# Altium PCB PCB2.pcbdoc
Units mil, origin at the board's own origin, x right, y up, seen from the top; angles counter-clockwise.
Board outline 3735.56 x 2015.12 mil, 2 copper layers (Top Layer, Bottom Layer); 65 components, 50 nets, 222 pads, 47 vias.
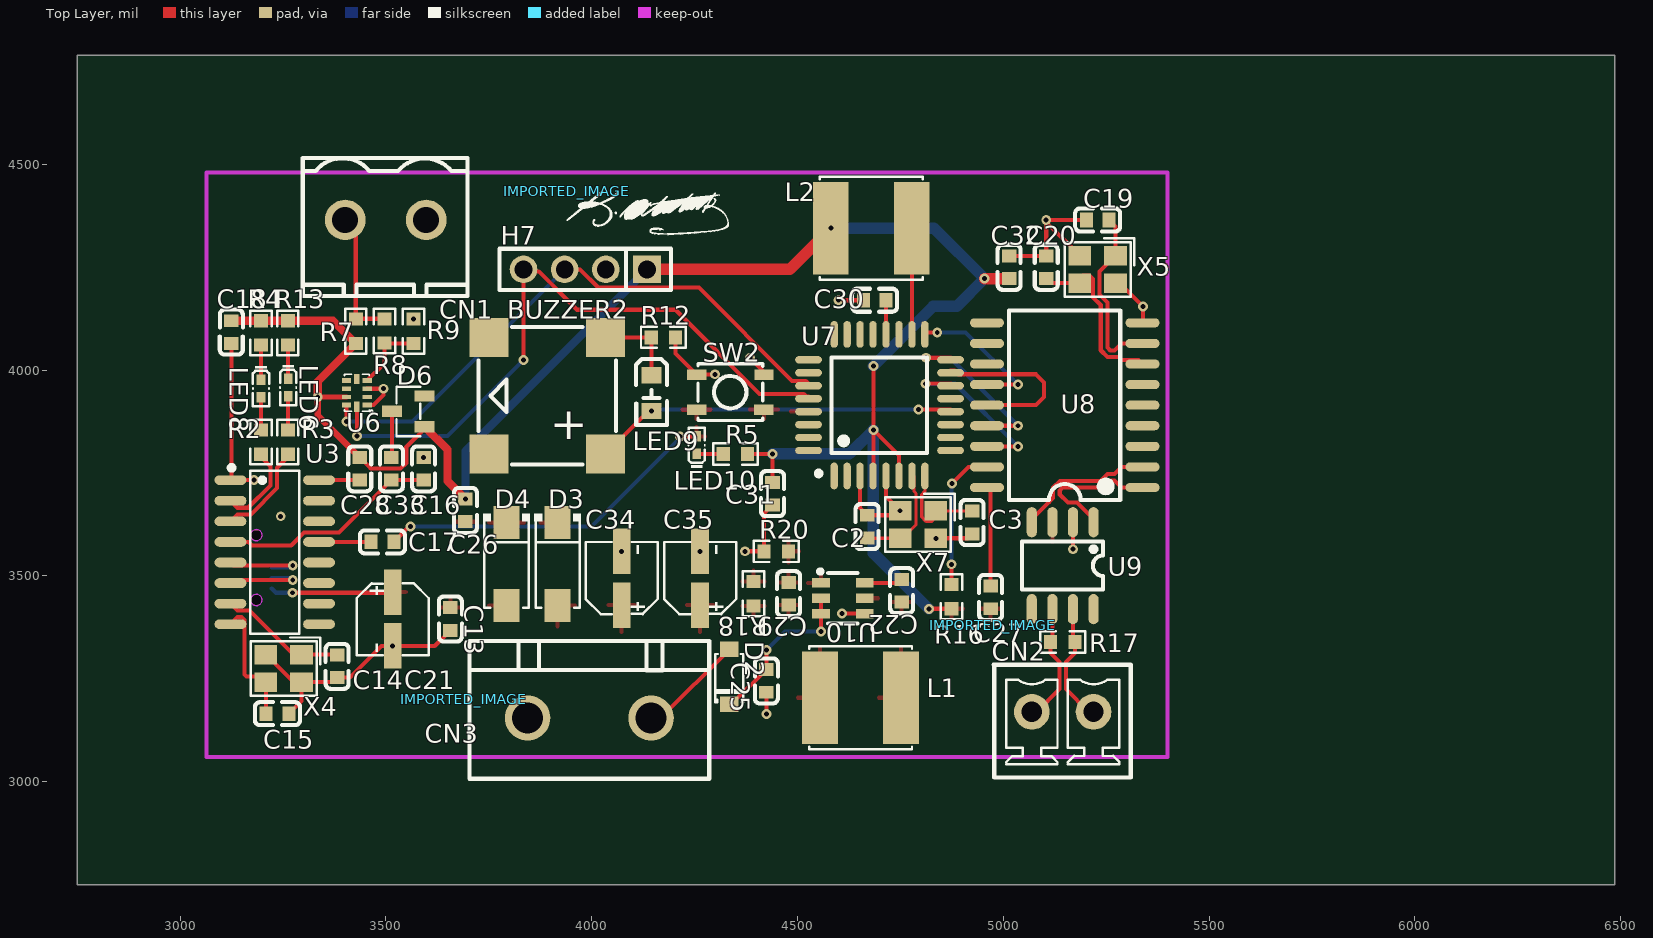
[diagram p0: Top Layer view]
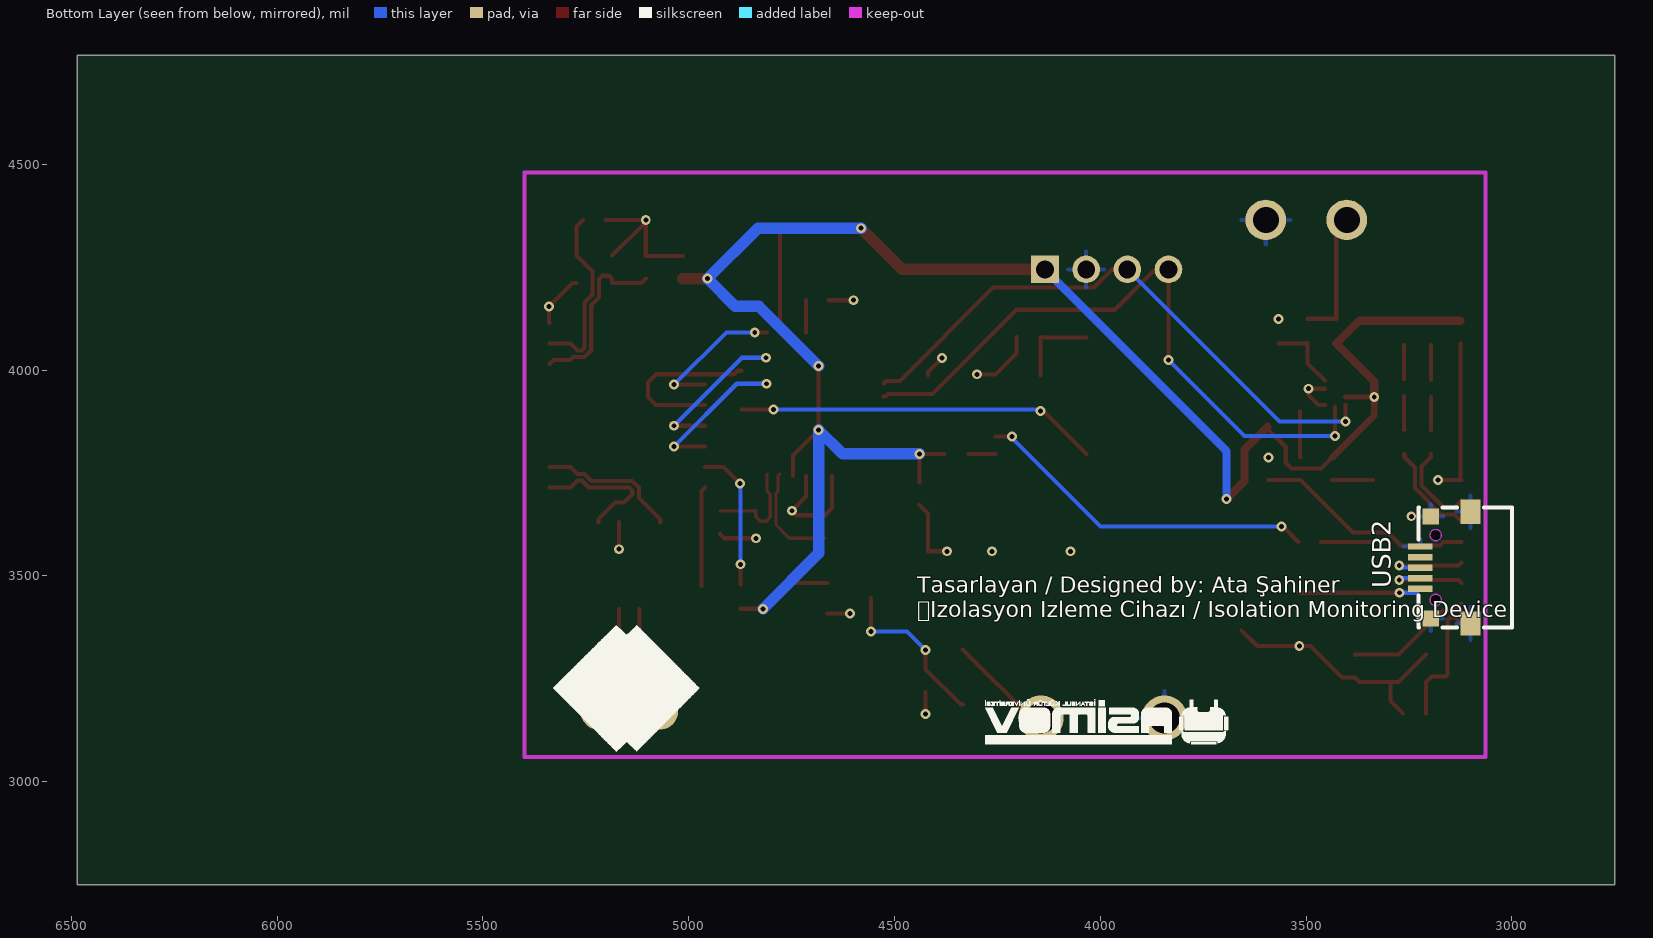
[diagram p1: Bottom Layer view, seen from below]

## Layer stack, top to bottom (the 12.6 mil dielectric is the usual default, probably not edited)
Top Layer: signal copper (thickness not stored)
Dielectric: dielectric 12.6, FR-4, Dk 4.8
Bottom Layer: signal copper (thickness not stored)

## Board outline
6485.56,2750 2750,2750 2750,4765.12 6485.56,4765.12

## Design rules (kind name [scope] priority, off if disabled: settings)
BoardOutlineClearance copperThickness1oz [All] p0: genericclearance=10 ignorepadtopadclearanceinfootprint=FALSE except(0: Arc-SplitContinuation Track-SplitContinuation SMDPad-SplitContinuation THPad-SplitContinuation Via-SplitContinuation Fill-SplitContinuation Poly-SplitContinuation Region-SplitContinuation Text-SplitContinuation; 6: Track-CutoutEdge SMDPad-CutoutEdge THPad-CutoutEdge Via-CutoutEdge Region-CutoutEdge; 11.8: Track-OutlineEdge SMDPad-OutlineEdge THPad-OutlineEdge Via-OutlineEdge Fill-OutlineEdge Region-OutlineEdge Poly-OutlineEdge Text-OutlineEdge Fill-CutoutEdge)
BoardOutlineClearance copperThickness2oz [All] p0: genericclearance=10 ignorepadtopadclearanceinfootprint=FALSE except(0: Arc-SplitContinuation Track-SplitContinuation SMDPad-SplitContinuation THPad-SplitContinuation Via-SplitContinuation Fill-SplitContinuation Poly-SplitContinuation Region-SplitContinuation Text-SplitContinuation; 6: Track-CutoutEdge SMDPad-CutoutEdge THPad-CutoutEdge Via-CutoutEdge Region-CutoutEdge; 11.8: Track-OutlineEdge SMDPad-OutlineEdge THPad-OutlineEdge Via-OutlineEdge Fill-OutlineEdge Region-OutlineEdge Poly-OutlineEdge Text-OutlineEdge Fill-CutoutEdge)
Clearance copperThickness1oz [(InNet('WARN') OR InNet('$1N38891') OR InNet('GND') OR InNet('XTAL1') OR InNet('XTAL2') OR InNet('$1N1971') OR InNet('$1N3263') OR InNet('$1N3302') OR InNet('RESET') OR InNet('+5V') OR InNet('$1N37233') OR InNet('$1N37305') OR InNet('$1N27741') OR InNet('$1N42220') OR InNet('$1N28334') OR InNet('$1N30372') OR InNet('$1N32358') OR InNet('$1N32397') OR InNet('$1N42230') OR InNet('$1N42278') OR InNet('$1N44015') OR InNet('$1N45861') OR InNet('$1N5233') OR InNet('$1N23722') OR InNet('$1N23715') OR InNet('$1N28331') OR InNet('SDA') OR InNet('SCL') OR InNet('$1N44013') OR InNet('$1N3088') OR InNet('TXD') OR InNet('$1N3089') OR InNet('RXD') OR InNet('$1N44197') OR InNet('AIN0') OR InNet('$1N13750') OR InNet('$1N2610') OR InNet('$1N2618') OR InNet('INT') OR InNet('AGND') OR InNet('SCK') OR InNet('SO') OR InNet('SI') OR InNet('CS') OR InNet('XI') OR InNet('XO') OR InNet('TXCAN') OR InNet('RXCAN') OR InNet('TXDC') OR InNet('RXDC'))] p1: gap=7 ignorepadtopadclearanceinfootprint=FALSE except(4: Track-Track; 6: Track-SMDPad SMDPad-SMDPad Track-THPad SMDPad-THPad THPad-THPad Track-Via SMDPad-Via THPad-Via Via-Via SMDPad-Fill THPad-Fill Via-Fill Fill-Fill Track-Region SMDPad-Region THPad-Region Via-Region Region-Region Track-Poly SMDPad-Poly THPad-Poly Via-Poly Fill-Poly Region-Poly Poly-Poly Track-Text SMDPad-Text THPad-Text Via-Text Fill-Text Region-Text Poly-Text Text-Text; 6.9: Track-Hole SMDPad-Hole THPad-Hole Via-Hole Fill-Hole Region-Hole Poly-Hole Text-Hole Sheet-Hole; 11.8: Track-Fill Fill-Region Track-Sheet SMDPad-Sheet THPad-Sheet Via-Sheet Fill-Sheet Region-Sheet Poly-Sheet Text-Sheet)
Clearance copperThickness2oz [All] p1: gap=7 ignorepadtopadclearanceinfootprint=FALSE except(6: Track-SMDPad SMDPad-SMDPad Track-THPad SMDPad-THPad THPad-THPad Track-Via SMDPad-Via THPad-Via Via-Via SMDPad-Fill THPad-Fill Via-Fill Fill-Fill Track-Region SMDPad-Region THPad-Region Via-Region Region-Region Track-Poly SMDPad-Poly THPad-Poly Via-Poly Fill-Poly Region-Poly Poly-Poly Track-Text SMDPad-Text THPad-Text Via-Text Fill-Text Region-Text Poly-Text Text-Text; 6.9: Track-Hole SMDPad-Hole THPad-Hole Via-Hole Fill-Hole Region-Hole Poly-Hole Text-Hole Sheet-Hole; 8: Track-Track; 11.8: Track-Fill Fill-Region Track-Sheet SMDPad-Sheet THPad-Sheet Via-Sheet Fill-Sheet Region-Sheet Poly-Sheet Text-Sheet)
DiffPairsRouting differentialPair [All] p1: maxuncoupledlength=10 minlimit=6 maxlimit=6 mostfreqgap=6 toplayer_minwidth=5 toplayer_prefwidth=10 toplayer_maxwidth=100 bottomlayer_minwidth=5 bottomlayer_prefwidth=10 bottomlayer_maxwidth=100
PasteMaskExpansion pasteMaskExpansion [All] p1: expansion=0
PlaneConnect innerPlane [All] p1: planeconnectstyle=Relief reliefexpansion=20 reliefentries=4 reliefconductorwidth=10 reliefairgap=10
PolygonConnect copperRegion [All] p1: connectstyle=Relief reliefentries=4 reliefconductorwidth=10 polygonreliefangle="90 Angle" airgapwidth=10
RoutingVias viaSize [All] p1: viastyle="Through Hole" holewidth=12.0078 minholewidth=11.811 maxholewidth=248.0314 width=24.0158 minwidth=19.685 maxwidth=393.7008
SolderMaskExpansion solderMaskExpansion [All] p1: useseparateexpansions=TRUE expansion=2 expansionbottom=2
Width copperThickness1oz [All] p1: maxlimit=100 minlimit=5 preferedwidth=10
Width copperThickness2oz [All] p1: maxlimit=100 minlimit=8 preferedwidth=10

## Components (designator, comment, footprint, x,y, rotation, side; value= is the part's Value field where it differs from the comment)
BUZZER2 "MLT-8530" BUZ-SMD_4P-L8.5-W8.5-P8.50-BR 3891.73,3937.78 r90 top
C2 "FCC1206N220J102DT" C0603 4669.23,3620 r90 top
C3 "FCC1206N220J102DT" C0603 4924.23,3630 r270 top
C13 "CC0603KRX7R9BB104" C0603 3656.42,3395.43 r90 top
C14 "FCC1206N220J102DT" C0603 3381.42,3280.43 r270 top
C15 "FCC1206N220J102DT" C0603 3236.42,3165.43 r0 top
C16 "CC0603KRX7R9BB104" C0603 3591.55,3760.31 r90 top
C17 "CC0603KRX7R9BB104" C0603 3491.42,3582.75 r180 top
C18 "CC0603KRX7R9BB104" C0603 3124.22,4092.52 r270 top
C19 "FCC1206N220J102DT" C0603 5229.23,4365 r180 top
C20 "FCC1206N220J102DT" C0603 5104.23,4250 r90 top
C21 "VT1H4R7M-CRC54" CAP-SMD_BD4.0-L4.3-W4.3-FD 3516.42,3395.43 r270 top
C22 "CC0603KRX7R9BB104" C0603 4753.06,3464.23 r90 top
C25 "CC0603KRX7R9BB104" C0603 4424.23,3245 r90 top
C26 "CC0603KRX7R9BB104" C0603 3693.06,3659.35 r90 top
C27 "CC0603KRX7R9BB104" C0603 4969.23,3447.92 r90 top
C28 "CC0603KRX7R9BB104" C0603 3436.42,3760.31 r90 top
C29 "CC0603KRX7R9BB104" C0603 4478.38,3456.97 r270 top
C30 "CC0603KRX7R9BB104" C0603 4687.41,4170 r0 top
C31 "CC0603KRX7R9BB104" C0603 4439.23,3700 r270 top
C32 "CC0603KRX7R9BB104" C0603 5014.23,4250 r270 top
C33 "CC0603KRX7R9BB104" C0603 3513.15,3760.31 r90 top
C34 "VT1H4R7M-CRC54" CAP-SMD_BD4.0-L4.3-W4.3-FD 4072.75,3494.54 r90 top
C35 "VT1H4R7M-CRC54" CAP-SMD_BD4.0-L4.3-W4.3-FD 4263.36,3494.54 r90 top
CN1 "WJ2EDGV-5.08-2P_C8461" CONN-TH_WJ2EDGV-5.08-2P 3499.35,4365.12 r180 top
CN2 "WJ15EDGVC-3.81-2P_C8396" CONN-TH_WJ15EDGVC-3.81-2P 5144.23,3170 r0 top
CN3 "DB2EVC-7.62-2P-GN" CONN-TH_2P-P7.62_DB2EVC-7.62-2P 3994.22,3155 r0 top
D2 "BZT52C5V6_C173406" SOD-123_L2.8-W1.8-LS3.7-RD 4334.23,3255 r90 top
D3 "SS14_R1_00001" SMA_L4.4-W2.8-LS5.4-RD 3917.07,3529.22 r270 top
D4 "SS14_R1_00001" SMA_L4.4-W2.8-LS5.4-RD 3793.06,3529.23 r270 top
D6 "BZX84C5V1_R1_00001" SOT-23-3_L2.9-W1.3-P1.90-LS2.4-BR 3554.22,3900 r0 top
H7 "HDR-F_2.54_1x4P" HDR-TH_4P-P2.54-V-F 3984.22,4245 r180 top
IMPORTED_IMAGE "IMPORTED_IMAGE" IMPORTED_IMAGE 4974.23,3380 r0 top
IMPORTED_IMAGE "IMPORTED_IMAGE" IMPORTED_IMAGE 3939.22,4435 r0 top
IMPORTED_IMAGE "IMPORTED_IMAGE" IMPORTED_IMAGE 3689.22,3200 r0 top
L1 "ASPI-0628-100M-T1" IND-SMD_L6.0-W6.0 4653.06,3204.23 r180 top
L2 "ASPI-0628-100M-T1" IND-SMD_L6.0-W6.0 4679.54,4345 r180 top
LED6 "LED_0402-R" LED0402-RD_YELLOW 3262.39,3957.81 r270 top
LED8 "LED_0402-R" LED0402-RD_YELLOW 3196.42,3955.43 r270 top
LED9 "YLED0805B" LED0805-RD 4145.17,3944.34 r270 top
LED10 "LED_0402-R" LED0402-RD_YELLOW 4254.89,3817.96 r90 top
R2 "1k" R0603 3196.42,3825.43 r270 top
R3 "1k" R0603 3261.42,3825.43 r270 top
R4 "1k" R0603 3196.42,4090.43 r90 top
R5 "10k" R0603 4349.23,3796.77 r0 top
R7 "1M" R0603 3426.62,4094.88 r90 top
R8 "1M" R0603 3496.28,4095.22 r270 top
R9 "82k" R0603 3566.62,4094.88 r90 top
R12 "220" R0603 4174.23,4080 r180 top
R13 "1k" R0603 3261.42,4090.43 r90 top
R16 "10k" R0603 4874.23,3450 r90 top
R17 "120" R0603 5144.23,3339.39 r0 top
R18 "576k" R0603 4393.07,3456.97 r270 top
R20 "113k" R0603 4448.06,3559.92 r180 top
SW2 "PTS810SJS250SMTRLFS" SW-SMD_4P_PTS810SJM250SMTRLFS 4336.67,3946.56 r0 top
U3 "CH340G" SOIC-16_L9.9-W3.9-P1.27-LS6.0-BL 3229.81,3557.76 r270 top
U6 "ADS1115IRUGR" X2QFN-10_L2.0-W1.5-P0.50-BL 3429.22,3945 r90 top
U7 "ATMEGA328P-AU_C14877" TQFP-32_L7.0-W7.0-P0.80-LS9.0-BL 4699.23,3915 r0 top
U8 "MCP2515T-I/SO" SOIC-18_L11.6-W7.5-P1.27-LS10.3-BL 5149.23,3915 r90 top
U9 "TJA1050DRG" SOP-8_L4.9-W3.9-P1.27-LS6.0-BL 5144.23,3525 r180 top
U10 "AP63200WU-7" SOT-23-6_L2.9-W1.6-P0.95-LS2.8-BR 4610.2,3445.84 r180 top
USB2 "MICRO QTZB5.5" MICRO-USB-SMD_MICRO-QTZB5.5 3161.42,3520.43 r90 bottom
X4 "TAXM8M4RDBCCT2T" CRYSTAL-SMD_4P-L3.2-W2.5-BL 3251.42,3275.43 r180 top
X5 "TAXM8M4RDBCCT2T" CRYSTAL-SMD_4P-L3.2-W2.5-BL 5229.23,4245 r180 top
X7 "TAXM8M4RDBCCT2T" CRYSTAL-SMD_4P-L3.2-W2.5-BL 4792.69,3625 r180 top

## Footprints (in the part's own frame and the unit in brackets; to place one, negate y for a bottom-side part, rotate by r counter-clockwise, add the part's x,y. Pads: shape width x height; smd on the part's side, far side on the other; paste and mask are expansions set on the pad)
BUZ-SMD_4P-L8.5-W8.5-P8.50-BR [mil]
  rect 94.49x94.49 smd: 1(-141.72,-141.73) 2(141.73,-141.73) 3(141.72,141.72) 4(-141.72,141.73)
  silkscreen extent -167,-167 167,167
C0603 [mm]
  rect 0.8x0.9 smd: 1(-0.7,0) 2(0.7,0)
  silkscreen extent -1.39,-0.71 1.39,0.71
CAP-SMD_BD4.0-L4.3-W4.3-FD [mm]
  rect 2.8x1.1 smd: 1(-1.661,0) 2(1.661,0)
  silkscreen extent -2.22,-2.23 2.24,2.23
CONN-TH_2P-P7.62_DB2EVC-7.62-2P [mm]
  round 2.8 hole 1.9: 1(-3.81,0) 2(3.81,0)
  silkscreen extent -7.4,-3.75 7.4,4.75
CONN-TH_WJ2EDGV-5.08-2P [mm]
  round 2.5 hole 1.6: 1(-2.499,0) 2(2.499,0)
  silkscreen extent -5.04,-3.81 5.12,4.7
CONN-TH_WJ15EDGVC-3.81-2P [mm]
  round 2.2 hole 1.25: 1(-1.905,0) 2(1.905,0)
  silkscreen extent -4.26,-4.06 4.2,2.9
CRYSTAL-SMD_4P-L3.2-W2.5-BL [mm]
  rect 1.4x1.2 smd: 1(-1.1,-0.85) 2(1.1,-0.85) 3(1.1,0.85) 4(-1.1,0.85)
  silkscreen extent -2.26,-1.91 2.03,1.68
HDR-TH_4P-P2.54-V-F [mm]
  rect 1.7x1.7 hole 1.1: 1(-3.81,0)
  round 1.7 hole 1.1: 2(-1.27,0) 3(1.27,0) 4(3.81,0)
  silkscreen extent -5.29,-1.27 5.29,1.27
IMPORTED_IMAGE [mil]
IND-SMD_L6.0-W6.0 [mm]
  rect 2.2x5.72 smd: 1(-2.5,0) 2(2.5,0)
  silkscreen extent -3.18,-3.18 3.18,3.18
LED0402-RD_YELLOW [mm]
  rect 0.636x0.54 smd: 1(-0.538,0) 2(0.538,0)
  silkscreen extent -1.39,-0.54 1.09,0.54
LED0805-RD [mm]
  rect 1x1.25 smd: 1(-1.1,0) 2(1.1,0)
  silkscreen extent -2.1,-0.95 1.98,0.96
MICRO-USB-SMD_MICRO-QTZB5.5 [mm]
  rect 0.4x1.524 smd: 1(-1.3,1.55) 2(-0.65,1.55) 3(0,1.55) 4(0.65,1.55) 5(1.3,1.55)
  rect 1.5x1.22 smd: 6(-3.45,-1.55) 7(3.45,-1.55)
  rect 1x1 smd: 6(-3.15,0.9) 7(3.15,0.9)
  Board Outline Layer circle w0.005: c-2,0.6 r0.35
  Board Outline Layer circle w0.005: c2,0.6 r0.35
  Board Outline Layer region: -2,0.95 -2.152,0.915 -2.274,0.818 -2.341,0.678 -2.341,0.522 -2.274,0.382 -2.152,0.285 -2,0.25 -2,0.25 -1.848,0.285 -1.726,0.382 -1.659,0.522 -1.659,0.678 -1.726,0.818 -1.848,0.915 -2,0.95
  Board Outline Layer region: 2,0.95 1.848,0.915 1.726,0.818 1.659,0.678 1.659,0.522 1.726,0.382 1.848,0.285 2,0.25 2,0.25 2.152,0.285 2.274,0.382 2.341,0.522 2.341,0.678 2.274,0.818 2.152,0.915 2,0.95
  Multi-Layer board cut-out: -2,0.95 -2.152,0.915 -2.274,0.818 -2.341,0.678 -2.341,0.522 -2.274,0.382 -2.152,0.285 -2,0.25 -2,0.25 -1.848,0.285 -1.726,0.382 -1.659,0.522 -1.659,0.678 -1.726,0.818 -1.848,0.915 -2,0.95
  Multi-Layer board cut-out: 2,0.95 1.848,0.915 1.726,0.818 1.659,0.678 1.659,0.522 1.726,0.382 1.848,0.285 2,0.25 2,0.25 2.152,0.285 2.274,0.382 2.341,0.522 2.341,0.678 2.274,0.818 2.152,0.915 2,0.95
  silkscreen extent -3.7,-4.1 3.7,1.65
R0603 [mil]
  rect 31.75x34.02 smd: 1(-29.66,0) 2(29.66,0)
  silkscreen extent -55,-26 55,26
SMA_L4.4-W2.8-LS5.4-RD [mil]
  rect 80.57x63.78 smd: 1(-101,0) 2(101,0)
  silkscreen extent -121,-57 106,57
SOD-123_L2.8-W1.8-LS3.7-RD [mm]
  rect 0.95x1.15 smd: 1(-1.692,0) 2(1.692,0)
  silkscreen extent -1.58,-0.87 1.41,0.87
SOIC-16_L9.9-W3.9-P1.27-LS6.0-BL [mil]
  oval 23.7x77.6 smd: 1(-175,-107.7) 2(-125,-107.7) 3(-75,-107.7) 4(-25,-107.7) 5(25,-107.7) 6(75,-107.7) 7(125,-107.7) 8(175,-107.7) 9(175,107.7) 10(125,107.7) 11(75,107.7) 12(25,107.7) 13(-25,107.7) 14(-75,107.7) 15(-125,107.7) 16(-175,107.7)
  silkscreen extent -211,-111 198,60
SOIC-18_L11.6-W7.5-P1.27-LS10.3-BL [mm]
  oval 0.56x2.1 smd: 1(-5.08,-4.8) 2(-3.81,-4.8) 3(-2.54,-4.8) 4(-1.27,-4.8) 5(0,-4.8) 6(1.27,-4.8) 7(2.54,-4.8) 8(3.81,-4.8) 9(5.08,-4.8) 10(5.08,4.8) 11(3.81,4.8) 12(2.54,4.8) 13(1.27,4.8) 14(0,4.8) 15(-1.27,4.8) 16(-2.54,4.8) 17(-3.81,4.8) 18(-5.08,4.8)
  silkscreen extent -5.84,-3.43 5.84,3.43
SOP-8_L4.9-W3.9-P1.27-LS6.0-BL [mm]
  oval 0.63x1.865 smd: 1(-1.905,-2.682) 2(-0.635,-2.682) 3(0.635,-2.682) 4(1.905,-2.682) 5(1.905,2.682) 6(0.635,2.682) 7(-0.635,2.682) 8(-1.905,2.682)
  silkscreen extent -2.5,-1.5 2.5,1.48
SOT-23-3_L2.9-W1.3-P1.90-LS2.4-BR [mm]
  rect 1.25x0.7 smd: 1(1,-0.95) 2(1,0.95) 3(-1,0)
  silkscreen extent -0.73,-1.53 0.73,1.53
SOT-23-6_L2.9-W1.6-P0.95-LS2.8-BR [mm]
  rect 1.1x0.6 smd: 1(1.35,-0.95) 2(1.35,0) 3(1.35,0.95) 4(-1.35,0.95) 5(-1.35,0) 6(-1.35,-0.95)
  silkscreen extent -0.9,-1.78 1.52,1.55
SW-SMD_4P_PTS810SJM250SMTRLFS [mm]
  rect 1.2x0.65 smd: 1(-2.078,1.083) 2(2.078,1.076) 3(-2.077,-1.083) 4(2.071,-1.075)
  silkscreen extent -2,-1.75 2,1.75
TQFP-32_L7.0-W7.0-P0.80-LS9.0-BL [mm]
  oval 0.45x1.65 smd: 1(-2.8,-4.369) 2(-2,-4.369) 3(-1.2,-4.369) 4(-0.4,-4.369) 5(0.4,-4.369) 6(1.2,-4.369) 7(2,-4.369) 8(2.8,-4.369) 17(2.8,4.369) 18(2,4.369) 19(1.2,4.369) 20(0.4,4.369) 21(-0.4,4.369) 22(-1.2,4.369) 23(-2,4.369) 24(-2.8,4.369)
  oval 1.65x0.45 smd: 9(4.381,-2.8) 10(4.381,-2) 11(4.381,-1.2) 12(4.381,-0.4) 13(4.381,0.4) 14(4.381,1.2) 15(4.381,2) 16(4.381,2.8) 25(-4.381,2.8) 26(-4.381,2) 27(-4.381,1.2) 28(-4.381,0.4) 29(-4.381,-0.4) 30(-4.381,-1.2) 31(-4.381,-2) 32(-4.381,-2.8)
  silkscreen extent -3.91,-4.36 2.94,2.95
X2QFN-10_L2.0-W1.5-P0.50-BL [mm]
  rect 0.3x0.58 smd: 1(-0.75,-0.635) 4(0.75,-0.635) 6(0.75,0.635) 9(-0.75,0.635)
  rect 0.25x0.58 smd: 2(-0.25,-0.635) 3(0.25,-0.635) 7(0.25,0.635) 8(-0.25,0.635)
  rect 0.63x0.35 smd: 5(0.86,0) 10(-0.86,0)
  silkscreen extent -1.22,-0.97 1.14,0.76

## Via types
v1: diameter 24.02, hole 12.01, Top Layer to Bottom Layer, 47 vias

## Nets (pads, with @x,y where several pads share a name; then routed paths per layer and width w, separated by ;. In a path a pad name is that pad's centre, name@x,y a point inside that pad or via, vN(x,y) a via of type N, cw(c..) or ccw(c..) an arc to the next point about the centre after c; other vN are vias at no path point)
$1N1971: C13.2 C21.1 D4.2 USB2.1 | length 298.8
  Top Layer w10: v1(3272.44,3459.25) 3514.86,3459.25 C21.1
  Bottom Layer w10: USB2.1 3232.44,3459.25 v1(3272.44,3459.25)
$1N2610: U3.5 USB2.3 | length 207.6
  Top Layer w10: U3.5 3129.45,3525.43 v1(3273.52,3525.43)
  Bottom Layer w10: USB2.3 3268.52,3520.43 v1(3273.52,3525.43)
$1N2618: U3.6 USB2.2 | length 207.5
  Top Layer w10: U3.6 3129.19,3489.84 v1(3273.52,3489.84)
  Bottom Layer w10: USB2.2 3268.52,3494.84 v1(3273.52,3489.84)
$1N3088: LED6.1 R13.1 | length 82.2
  Top Layer w10: R13.1 3262.39,4059.79 LED6.1
$1N3089: LED8.1 R4.1 | length 84.2
  Top Layer w10: LED8.1 R4.1
$1N3263: C16.1 C33.1 U3.4 | length 538.5
  Top Layer w10: U3.4 3166.42,3582.76 3174.78,3574.4 3269.91,3574.4 3301.1,3605.6 3386,3605.6 C33.1 C16.1
$1N3302: C17.2 U3.13 | length 126.3
  Top Layer w10: U3.13@3337.52,3582.75 C17.2
$1N5233: CN1.2 R7.2 R8.1 | length 321
  Top Layer w10: CN1.2 3426.62,4339.45 R7.2 3426.96,4124.88 R8.1
$1N13750: R16.2 U8.17 | length 347.3
  Top Layer w10: R16.2 v1(4874.23,3528.38) ; v1(4875.24,3725) 4915.24,3765 U8.17
  Bottom Layer w10: v1(4874.23,3528.38) 4874.23,3723.98 v1(4875.24,3725)
$1N23715: CN2.2 R17.2 U9.7 | length 295.1
  Top Layer w10: U9.7 5169.23,3350.68 5173.89,3346.02 R17.2 5173.89,3312.39 5152.23,3290.73 5152.23,3225 5207.23,3170 CN2.2
$1N23722: CN2.1 R17.1 U9.6 | length 295.1
  Top Layer w10: CN2.1 5081.23,3170 5136.23,3225 5136.23,3290.73 5114.56,3312.39 R17.1 5114.56,3346.02 5119.23,3350.68 U9.6
$1N27741: C22.2 U10.6 | length 93.3
  Top Layer w10: U10.6 4744.5,3483.24 C22.2
$1N28331: CN3.2 D2.2 | length 259
  Top Layer w10: CN3.2 4167.6,3155 D2.2
$1N28334: C25.2 D2.1 U10.2 U10.3 | length 404.6
  Top Layer w10: D2.1 4340.03,3188.37 C25.2 v1(4424.23,3320) ; v1(4557.06,3365) U10.3 U10.2
  Bottom Layer w10: v1(4424.23,3320) 4469.23,3365 v1(4557.06,3365)
$1N30372: C26.1 D3.1 D4.1
$1N32358: C27.2 U8.18 | length 243.2
  Top Layer w10: U8.18 4969.23,3706.02 C27.2
$1N32397: C28.1 U3.16 | length 98.9
  Top Layer w10: U3.16@3337.52,3732.75 C28.1
$1N37233: C19.1 U8.8 X5.1 | length 435.6
  Top Layer w10: C19.1 5272.53,4349.25 X5.1 5233.99,4239.92 5233.99,4183.36 5252.8,4164.56 5252.8,4055.07 5259.87,4048 5269.87,4048 5286.87,4065 U8.8
$1N37305: C20.1 U8.7 X5.3 | length 430.9
  Top Layer w10: C20.1 5115.13,4211.54 X5.3 5185.91,4221.54 5193.96,4229.58 5209.65,4229.58 5217.99,4221.23 5217.99,4176.74 5236.8,4157.93 5236.8,4048.44 5253.24,4032 5279.87,4032 5286.87,4025 5328.2,4025 U8.7
$1N38891: BUZZER2.2 LED9.1 R12.2 | length 203.9
  Top Layer w10: BUZZER2.2 4144.07,4079.51 R12.2 4145.18,4079.39 LED9.1
$1N42220: C22.1 L1.1 U10.5
$1N42230: C29.2 C34.1 C35.1 D3.2 L1.2 R18.2
$1N42278: C29.1 R18.1 R20.1 U10.1
$1N44013: L2.1 U7.18 | length 253
  Top Layer w10: U7.18@4777.95,4091.99 L2.1
$1N44015: C30.2 U7.20 | length 78
  Top Layer w10: U7.20@4714.97,4092 C30.2
$1N44197: LED10.1 R5.1 | length 64.7
  Top Layer w10: LED10.1 R5.1
$1N45861: C33.2 D6.3 | length 112.8
  Top Layer w10: C33.2 3514.86,3789.57 D6.3
+5V: C18.1 C26.2 C27.1 C28.2 C31.1 C32.2 D6.1 H7.1 L2.2 R4.2 R5.2 R7.1 R13.2 R16.1 U6.8 U7.4 U7.6 U9.3 | length 4626.5
  Top Layer w10: C28.2 3463.15,3761.14 3535.42,3761.14 3549.22,3774.94 3549.22,3813.23 3593.59,3857.6 D6.1 ; R5.2 v1(4439.23,3796.77) C31.1 ; U7.4 4684.23,3743.75 v1(4684.23,3855) ; v1(4684.23,4010) v1(4684.23,3855) ; U7.6 4746.47,3792.76 v1(4684.23,3855) ; v1(4819.23,3420) 4819.56,3420.34 R16.1
  Top Layer w11.81: v1(3334.22,3935) 3334.39,3935.16 U6.8
  Top Layer w15.75: v1(3334.22,3935) 3334.22,3890.06 C28.2
  Top Layer w19.68: C18.1 R4.2 R13.2 3371.75,4120.09 R7.1 3334.22,3972.82 v1(3334.22,3935) ; D6.1 3649.22,3806.97 3649.22,3730.75 v1(3693.06,3686.91)
  Top Layer w27.56: H7.1 4481.12,4245 v1(4581.12,4345) ; v1(4954.23,4222.44) C32.2
  Bottom Layer w19.68: v1(3693.06,3686.91) 3693.06,3803.84 H7.1
  Bottom Layer w27.56: v1(4439.23,3796.77) 4626,3796.77 v1(4684.23,3855) 4684.23,3555 v1(4819.23,3420) ; v1(4581.12,4345) 4831.67,4345 v1(4954.23,4222.44) 4886.78,4155 4829.23,4155 v1(4684.23,4010)
AGND: U7.21
AIN0: R8.2 R9.1 U6.4 | length 178.9
  Top Layer w10: U6.4 3496.28,4016.59 R8.2 3496.62,4065.22 R9.1
CS: U7.14 U8.16 | length 423.2
  Top Layer w10: v1(4810.93,3966.99) 4811.17,3967.24 U7.14@4871.71,3967.24 ; U8.16 v1(5035.24,3815)
  Bottom Layer w10: v1(4810.93,3966.99) 4883.25,3966.99 v1(5035.24,3815)
GND: C2.2 C3.2 C13.1 C14.2 C15.2 C16.2 C18.2 C19.2 C20.2 C21.2 C25.1 C30.1 C31.2 C32.1 C34.2 C35.2 CN1.1 CN3.1 H7.2 R9.2 R12.1 R20.2 SW2.1 SW2.2 U3.1 U6.1 U6.3 U7.3 U7.5 U8.9 U9.2 U10.4 USB2.5 USB2.6 USB2.7 X4.2 X4.4 X5.2 X5.4 X7.2 X7.4 | length 2620.6
  Top Layer w10: C18.2 3124.22,3734.87 U3.1 v1(3179.22,3732.76) ; X4.2 3275.04,3241.96 X4.4 ; C15.2 3294.73,3196.18 X4.4 ; U6.1 3469.7,3915.47 3494.22,3940 v1(3494.22,3955) 3494.07,3954.84 U6.3 ; C13.1 3618.6,3330.05 v1(3516.42,3330.05) 3489.27,3330.05 3412.09,3252.87 C14.2 3370.51,3241.96 X4.4 ; R12.1 4203.89,4040.19 SW2.1 4298.43,3989.2 v1(4299.23,3990) ; v1(4372.26,3559.92) R20.2 4418.4,3651.61 C31.2 ; v1(4384.23,4030) 4418.47,3995.75 SW2.2 ; v1(4424.23,3165) C25.1 ; v1(4599.23,4170) C30.1 ; v1(4608.35,3408.44) U10.4 ; U7.3 4651.98,3664.8 C2.2 4738.47,3647.56 v1(4749.38,3658.47) 4714.97,3692.87 U7.5 ; v1(4836,3591.54) 4913.32,3591.54 C3.2 ; C32.1 C20.2 5104.23,4360.16 X5.2 ; v1(5104.23,4365) C19.2 ; v1(5169.23,3565) U9.2 ; X5.4 5282.69,4211.54 v1(5339.23,4155) 5339.23,4116.02 U8.9
  other v1: 4072.75,3559.91 4262.75,3559.91 3244.22,3645 3591.55,3787.87 3566.62,4124.54
INT: U7.32
RESET: C17.1 LED10.2 SW2.3 SW2.4 U7.29 | length 840.4
  Top Layer w10: C17.1 3556.23,3620 v1(3559.22,3620) ; v1(4214.76,3839.13) LED10.2
  Bottom Layer w10: v1(3559.22,3620) 3999.76,3620 v1@4214.76,3835
RXCAN: U8.2 U9.4 | length 343.8
  Top Layer w10: U9.4 5069.23,3637.99 5109.54,3678.31 5110.29,3678.31 5121.15,3689.17 5121.15,3714.56 5137.6,3731 5236.24,3731 5253.24,3748 5269.87,3748 5286.87,3765 U8.2
RXD: LED8.2 R2.1 | length 79.2
  Top Layer w10: R2.1 LED8.2
RXDC: R3.2 U3.3 | length 239.7
  Top Layer w10: U3.3 3139.11,3649.76 3171.61,3649.76 3235.22,3713.37 3235.22,3762.95 3261.42,3789.14 R3.2
SCK: U7.17 U8.13 | length 353.4
  Top Layer w10: U7.17@4809.45,4091.99 v1(4839.45,4091.99) ; U8.13 v1(5035.24,3965)
  Bottom Layer w10: v1(4839.45,4091.99) 4908.25,4091.99 v1(5035.24,3965)
SCL: H7.4 U6.10 U7.28 | length 1593.4
  Top Layer w10: v1(3429.22,3840) U6.10 ; v1(3834.22,4025) H7.4 3839.22,4240 3871.36,4240 3964.52,4146.85 4203.58,4146.85 4408.03,3942.39 4515.06,3942.39 4521.71,3935.74 U7.28@4526.71,3935.74
  Bottom Layer w10: v1(3429.22,3840) 3649.22,3840 v1(3834.22,4025)
SDA: H7.3 U6.9 U7.27 | length 1431.3
  Top Layer w10: v1(3404.22,3875) U6.9 ; H7.3 3971.36,4245 4015.81,4200.55 4260.34,4200.55 4486.99,3973.9 4520.05,3973.9 U7.27@4526.71,3967.24
  Bottom Layer w10: v1(3404.22,3875) 3564.22,3875 H7.3
SI: U7.15 U8.14 | length 421.7
  Top Layer w10: U7.15@4871.71,3998.73 4881.71,3998.73 4890.44,3990 5079.23,3990 5099.23,3970 5099.23,3935 5079.23,3915 U8.14
SO: U7.16 U8.15 | length 427
  Top Layer w10: v1(4811.71,4030.23) U7.16@4871.71,4030.23 ; U8.15 v1(5035.24,3865)
  Bottom Layer w10: v1(4811.71,4030.23) 4870.02,4030.23 v1(5035.24,3865)
TXCAN: U8.1 U9.1 | length 342.3
  Top Layer w10: U9.1 5219.23,3637.99 5178.91,3678.31 5156.78,3678.31 5137.15,3697.93 5137.15,3707.93 5144.23,3715 5242.87,3715 5259.87,3732 5269.87,3732 5286.87,3715 U8.1
TXD: LED6.2 R3.1 | length 81.9
  Top Layer w10: R3.1 3262.39,3856.06 LED6.2
TXDC: R2.2 U3.2 | length 211.8
  Top Layer w10: U3.2 3139.11,3665.76 3164.99,3665.76 3219.22,3720 3219.22,3766.33 3196.42,3789.14 R2.2
WARN: BUZZER2.1 LED9.2 U7.12 | length 883.1
  Top Layer w10: BUZZER2.1 4138.44,3901.03 v1(4145.18,3901.03) ; v1@4794.23,3904.24 U7.12@4871.71,3904.24
  Bottom Layer w10: v1(4145.18,3901.03) 4148.4,3904.25 v1(4794.23,3904.25)
XI: C14.1 U3.7 X4.1 | length 311
  Top Layer w10: U3.7 3139.11,3415.76 3167.95,3415.76 3274.82,3308.89 X4.1 3380.51,3308.89 C14.1
XO: C15.1 U3.8 X4.3 | length 312.6
  Top Layer w10: U3.8 3139.11,3399.76 3149.11,3399.76 3156.18,3392.69 3156.18,3260.66 3161.18,3255.66 3194.41,3255.66 X4.3 3208.11,3166.18 C15.1
XTAL1: C2.1 U7.7 X7.3 | length 260.4
  Top Layer w7.87: C2.1 4674.23,3592.44 4675.13,3591.54 4755.25,3591.54 4787.83,3624.12 4787.83,3700.64 4782.95,3705.51 4782.95,3742.99 U7.7@4777.95,3747.99
XTAL2: C3.1 U7.8 X7.1 | length 253.8
  Top Layer w7.87: U7.8@4809.45,3747.99 4809.45,3705.51 4801.7,3697.76 4801.7,3643.6 4812.09,3633.21 4826.23,3633.21 4836.87,3643.85 4836.87,3658.47 4837.77,3657.56 C3.1
pads on no net: BUZZER2.3 BUZZER2.4 D6.2 U3.9 U3.10 U3.11 U3.12 U3.14 U3.15 U6.2 U6.5 U6.6 U6.7 U7.1 U7.2 U7.9 U7.10 U7.11 U7.13 U7.19 U7.22 U7.23 U7.24 U7.25 U7.26 U7.30 U7.31 U8.3 U8.4 U8.5 U8.6 U8.10 U8.11 U8.12 U9.5 U9.8 USB2.4

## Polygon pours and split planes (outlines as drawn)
GND on Bottom Layer (solid, remove dead copper, pour order 14): 3079.22,4425 5364.23,4425 5364.23,3100 3079.22,3100
$1N42220 on Top Layer (solid, remove dead copper, pour order 4): 4793.03,3464.23 4793.03,3090.43 4641.42,3090.43 4641.42,3464.23
$1N30372 on Top Layer (solid, remove dead copper, pour order 6): 3951.42,3675.43 3951.42,3604.23 3654.77,3604.23 3654.77,3675.43
$1N1971 on Top Layer (solid, remove dead copper, pour order 8): 3831.42,3470.43 3831.42,3395.43 3469.94,3395.43 3469.94,3470.43
$1N42278 on Top Layer (solid, remove dead copper, pour order 0): 4506.42,3595.43 4581.42,3520.43 4581.42,3460.43 4356.42,3460.43 4356.42,3515.43 4366.42,3525.43 4441.15,3525.43 4441.15,3580.16 4456.42,3595.43
$1N42230 on Top Layer (solid, remove dead copper, pour order 2): 4596.42,3085.43 4596.42,3320.43 4576.42,3340.43 4516.42,3340.43 4516.42,3456.97 3879.87,3456.97 3876.42,3460.43 3876.42,3385.43 3911.42,3350.43 4466.42,3350.43 4466.42,3100.43 4481.42,3085.43
+5V on Top Layer (solid, remove dead copper, pour order 10): 5144.23,3669.39 5144.23,3530 4999.23,3385 4839.23,3385 4839.23,3433.22 4856.01,3450 5014.23,3450 5100.39,3536.17 5100.39,3669.16 5144,3669.16
RESET on Top Layer (solid, remove dead copper, pour order 12): 4204.23,3920 4204.23,3824.46 4204.05,3824.29 4433.51,3824.29 4494.23,3885 4559.23,3885 4564.23,3890 4564.23,3910 4559.23,3915 4464.23,3915 4459.23,3920

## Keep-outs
Board Outline Layer:
  lines w10: 3064.22,3060 5399.23,3060 5399.23,4480 3064.22,4480 3064.22,3060

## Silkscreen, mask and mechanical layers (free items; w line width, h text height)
Bottom Silkscreen Layer:
  text "Tasarlayan / Designed by: Ata Şahiner /  Izolasyon Izleme Cihazı / Isolation Monitoring Device" at 4444.23,3400 h39.37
